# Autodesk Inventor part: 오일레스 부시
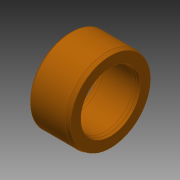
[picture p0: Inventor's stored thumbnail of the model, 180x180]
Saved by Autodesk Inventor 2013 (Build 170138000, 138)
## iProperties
Created: 2024-02
Part Number: 오일레스 부시
Material: 강철, 합금
Document SubType Name: Modeling
Designer: mdu-01
Density: 1 g/cm^3
Author: mdu-01
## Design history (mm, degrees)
sketch "스케치1"
  geometry: L1 (0, 0)-(10, 0); L2 (1.395, 7)-(8.605, 7); L3 (10, 7.268)-(10, 9.732); L4 (9, 10)-(0.5, 10); L5 (0, 9.5)-(0, 7.268); L6 (9, 10)-(10, 9.732); L7 (9.381, 7.102)-(10, 7.268); L8 (0.619, 7.102)-(0, 7.268); L9 (0.5, 10)-(0, 9.5); A1 r 3 centre (1.395, 10) between (0.619, 7.102) and (1.395, 7); A2 r 3 centre (8.605, 10) between (8.605, 7) and (9.381, 7.102); 6 further points
  constraints: 18 end point, 14 point on line, 4 point on circle, 4 tangent, 2 centre point, 2 horizontal, 2 parallel, 1 equal radius, 1 perpendicular
  dimensions: "d0" = 10 distance of L1.start L1.end; "d1" = 14 diameter of L2 L1; "d2" = 20 diameter of L4 L1; "d3" = 1 distance of L4.start point (10, 10); "d4" = 15 deg angle of L4 L6; "d5" = 1 distance of point (9, 7) point (10, 7) (= d3); "d6" = 15 deg angle of L2 L7 (= d4); "d7" = 1 distance of point (1, 7) point (0, 7) (= d3); "d8" = 15 deg angle of L2 L8 (= d4); "d9" = 3 radius of A1; "d10" = 0.5 distance of L4.end point (0, 10); "d11" = 0.5 distance of L5.start point (0, 10) (= d10)
revolve "회전1" sketch "스케치1" stored, may be unused: angle "d12" = 90 deg
node "솔리드1"
